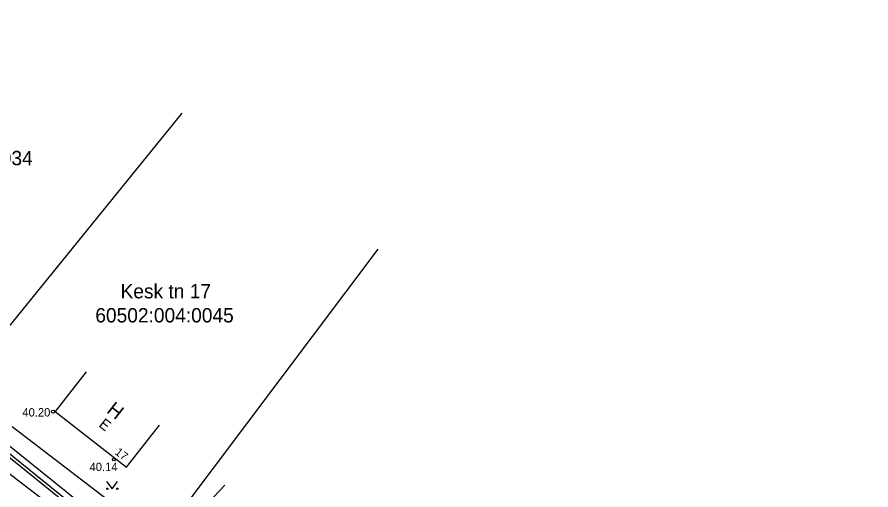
# Model space of a CAD drawing. Extents: x 641898 to 642452, y 6471715 to 6472255.
# Drawn here: x 642175.8 to 642247.4, y 6471955.1 to 6471994.7 of the extents above; entities that cross this region are included whole.
import ezdxf

# ---------------------------------------------------------------- set-up
doc = ezdxf.new("R2010")
doc.units = 0
for name, color, linetype in [('HALJASTUS', 7, 'Continuous'), ('HOONE', 7, 'Continuous'), ('KORGUS-EH2000', 7, 'Continuous'), ('MPOHULIIN', 7, 'Continuous'), ('PIIR', 7, 'Continuous'), ('TEE', 7, 'Continuous'), ('VTRASS', 7, 'Continuous')]:
    doc.layers.add(name, color=color, linetype=linetype)

msp = doc.modelspace()

# ---------------------------------------------------------------- linework, layer by layer
at = {"layer": 'HALJASTUS'}
for p, q in [((642183.314, 6471955.806), (642183.778, 6471955.199)), ((642183.778, 6471955.199), (642184.223, 6471955.806))]:
    msp.add_line(p, q, dxfattribs=at)
for points in [[(642182.798, 6471951.948), (642174.449, 6471958.694), (642170.419, 6471961.008)], [(642186.905, 6471948.809), (642193.214, 6471955.496)]]:
    msp.add_lwpolyline(points, dxfattribs=at)
for centre in [(642183.377, 6471955.199), (642184.206, 6471955.199)]:
    msp.add_circle(centre, 0.055, dxfattribs=at)
at = {"layer": 'HOONE'}
msp.add_lwpolyline([(642181.592, 6471964.98), (642178.996, 6471961.668), (642184.964, 6471956.991), (642187.736, 6471960.527)], dxfattribs=at)
at = {"layer": 'KORGUS-EH2000'}
for centre in [(642178.82, 6471961.646), (642183.919, 6471957.648)]:
    msp.add_circle(centre, 0.125, dxfattribs=at)
at = {"layer": 'MPOHULIIN'}
msp.add_lwpolyline([(642355.522, 6471813.313), (642331.534, 6471832.393), (642302.222, 6471855.921), (642271.629, 6471880.301), (642234.793, 6471909.555), (642198.436, 6471939.015), (642169.975, 6471961.956), (642133.076, 6471995.171), (642102.99, 6472021.089), (642074.552, 6472045.947), (642044.597, 6472041.824), (642019.939, 6472060.923), (641980.015, 6472091.706), (641945.513, 6472065.466), (641932.178, 6472056.628)], dxfattribs=at)
at = {"layer": 'PIIR'}
for p, q in [((642189.602, 6471986.63), (642170.2, 6471962.73)), ((642186.7, 6471949.52), (642206.053, 6471975.244)), ((642186.7, 6471949.52), (642170.2, 6471962.73))]:
    msp.add_line(p, q, dxfattribs=at)
at = {"layer": 'TEE'}
msp.add_lwpolyline([(642214.441, 6471935.082), (642210.265, 6471931.295), (642208.667, 6471929.555), (642200.55, 6471936.024), (642192.814, 6471942.275), (642187.251, 6471946.896), (642181.726, 6471951.396), (642174.008, 6471957.307), (642163.973, 6471965.281), (642157.225, 6471970.564), (642154.958, 6471971.99)], dxfattribs=at)
at = {"layer": 'VTRASS'}
msp.add_lwpolyline([(642261.241, 6471893.85), (642226.798, 6471920.874), (642223.555, 6471923.471), (642220.019, 6471926.258), (642175.39, 6471960.391)], dxfattribs=at)

# ---------------------------------------------------------------- texts
at = {"layer": 'HOONE'}
for s, height, rotation, p in [('H', 1.2, 321.9081, (642183.234, 6471961.625)), ('E', 0.9, 321.9081, (642182.589, 6471960.45)), ('17', 0.7, 321.90811, (642183.937, 6471958.145))]:
    msp.add_text(s, height=height, rotation=rotation, dxfattribs=at).set_placement(p)
at = {"layer": 'KORGUS-EH2000'}
for s, p in [('40.20', (642176.25, 6471961.243)), ('40.14', (642181.882, 6471956.674))]:
    msp.add_text(s, height=0.7, dxfattribs=at).set_placement(p)
at = {"layer": 'PIIR'}
for s, p in [('60502:004:0034', (642165.517, 6471982.278)), ('Kesk tn 17', (642184.478, 6471971.132)), ('60502:004:0045', (642182.364, 6471969.117))]:
    msp.add_text(s, height=1.2, dxfattribs=at).set_placement(p)

doc.saveas('drawing.dxf')
